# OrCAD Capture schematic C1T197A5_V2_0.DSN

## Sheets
1 00_Log: title: Telink-Semi; rev: V2.0; note: C1T197A5
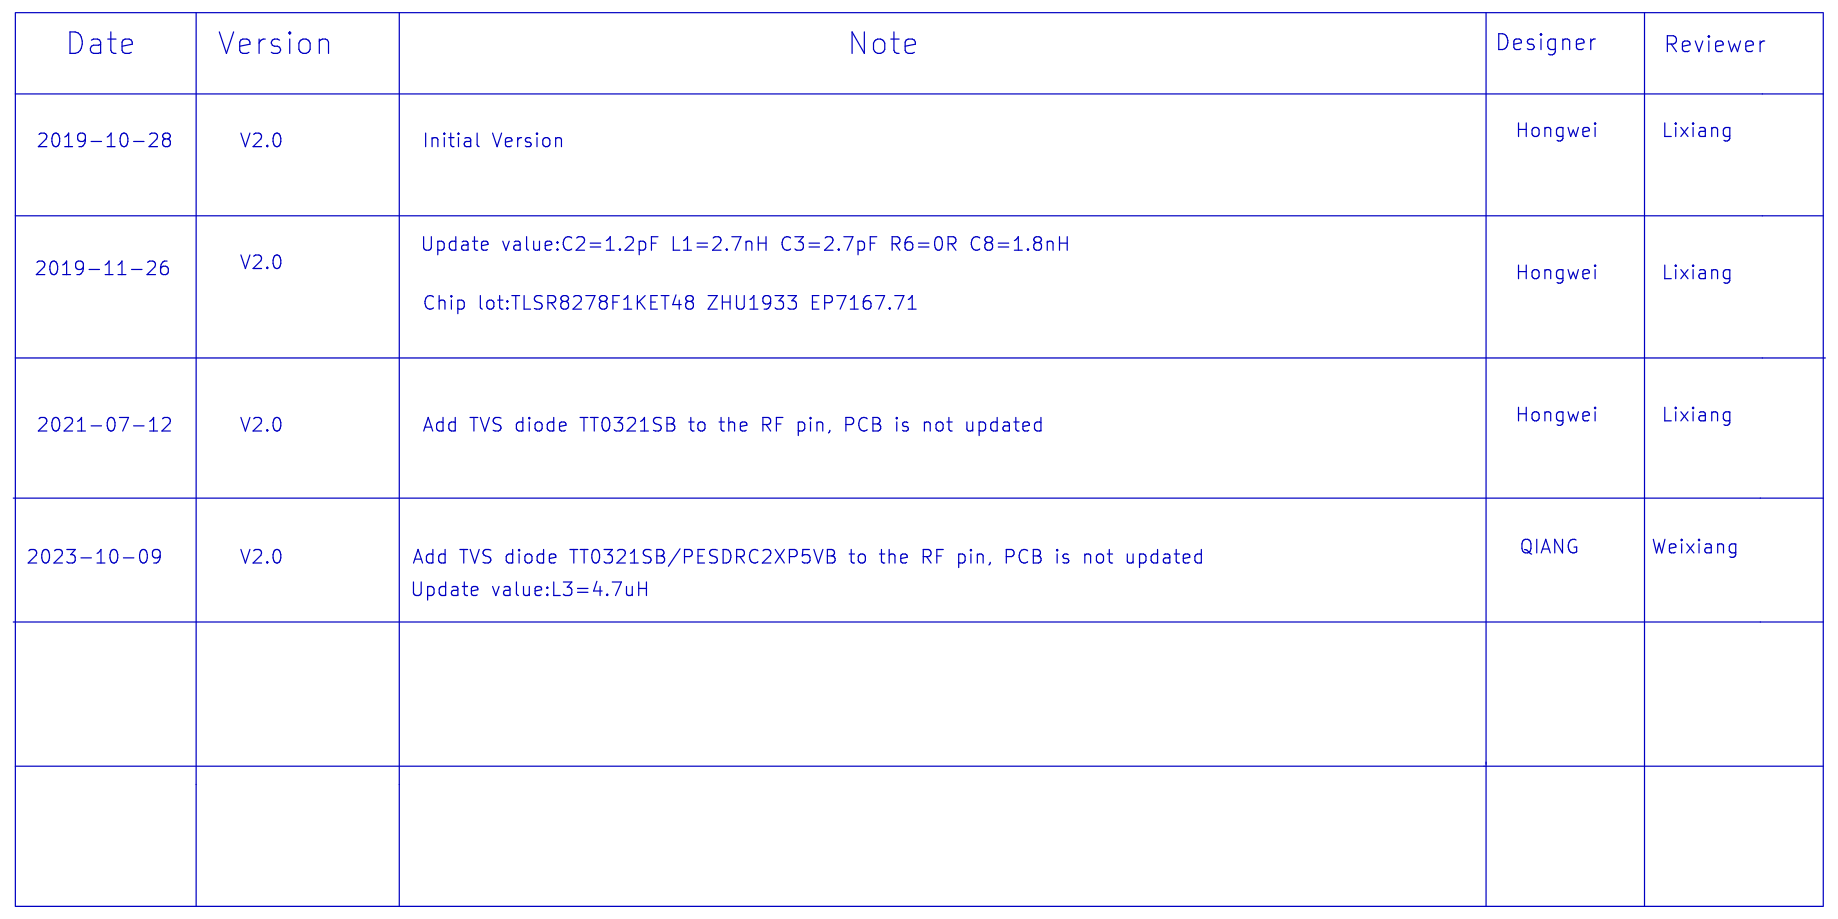
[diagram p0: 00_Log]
2 01_CPU: size A4
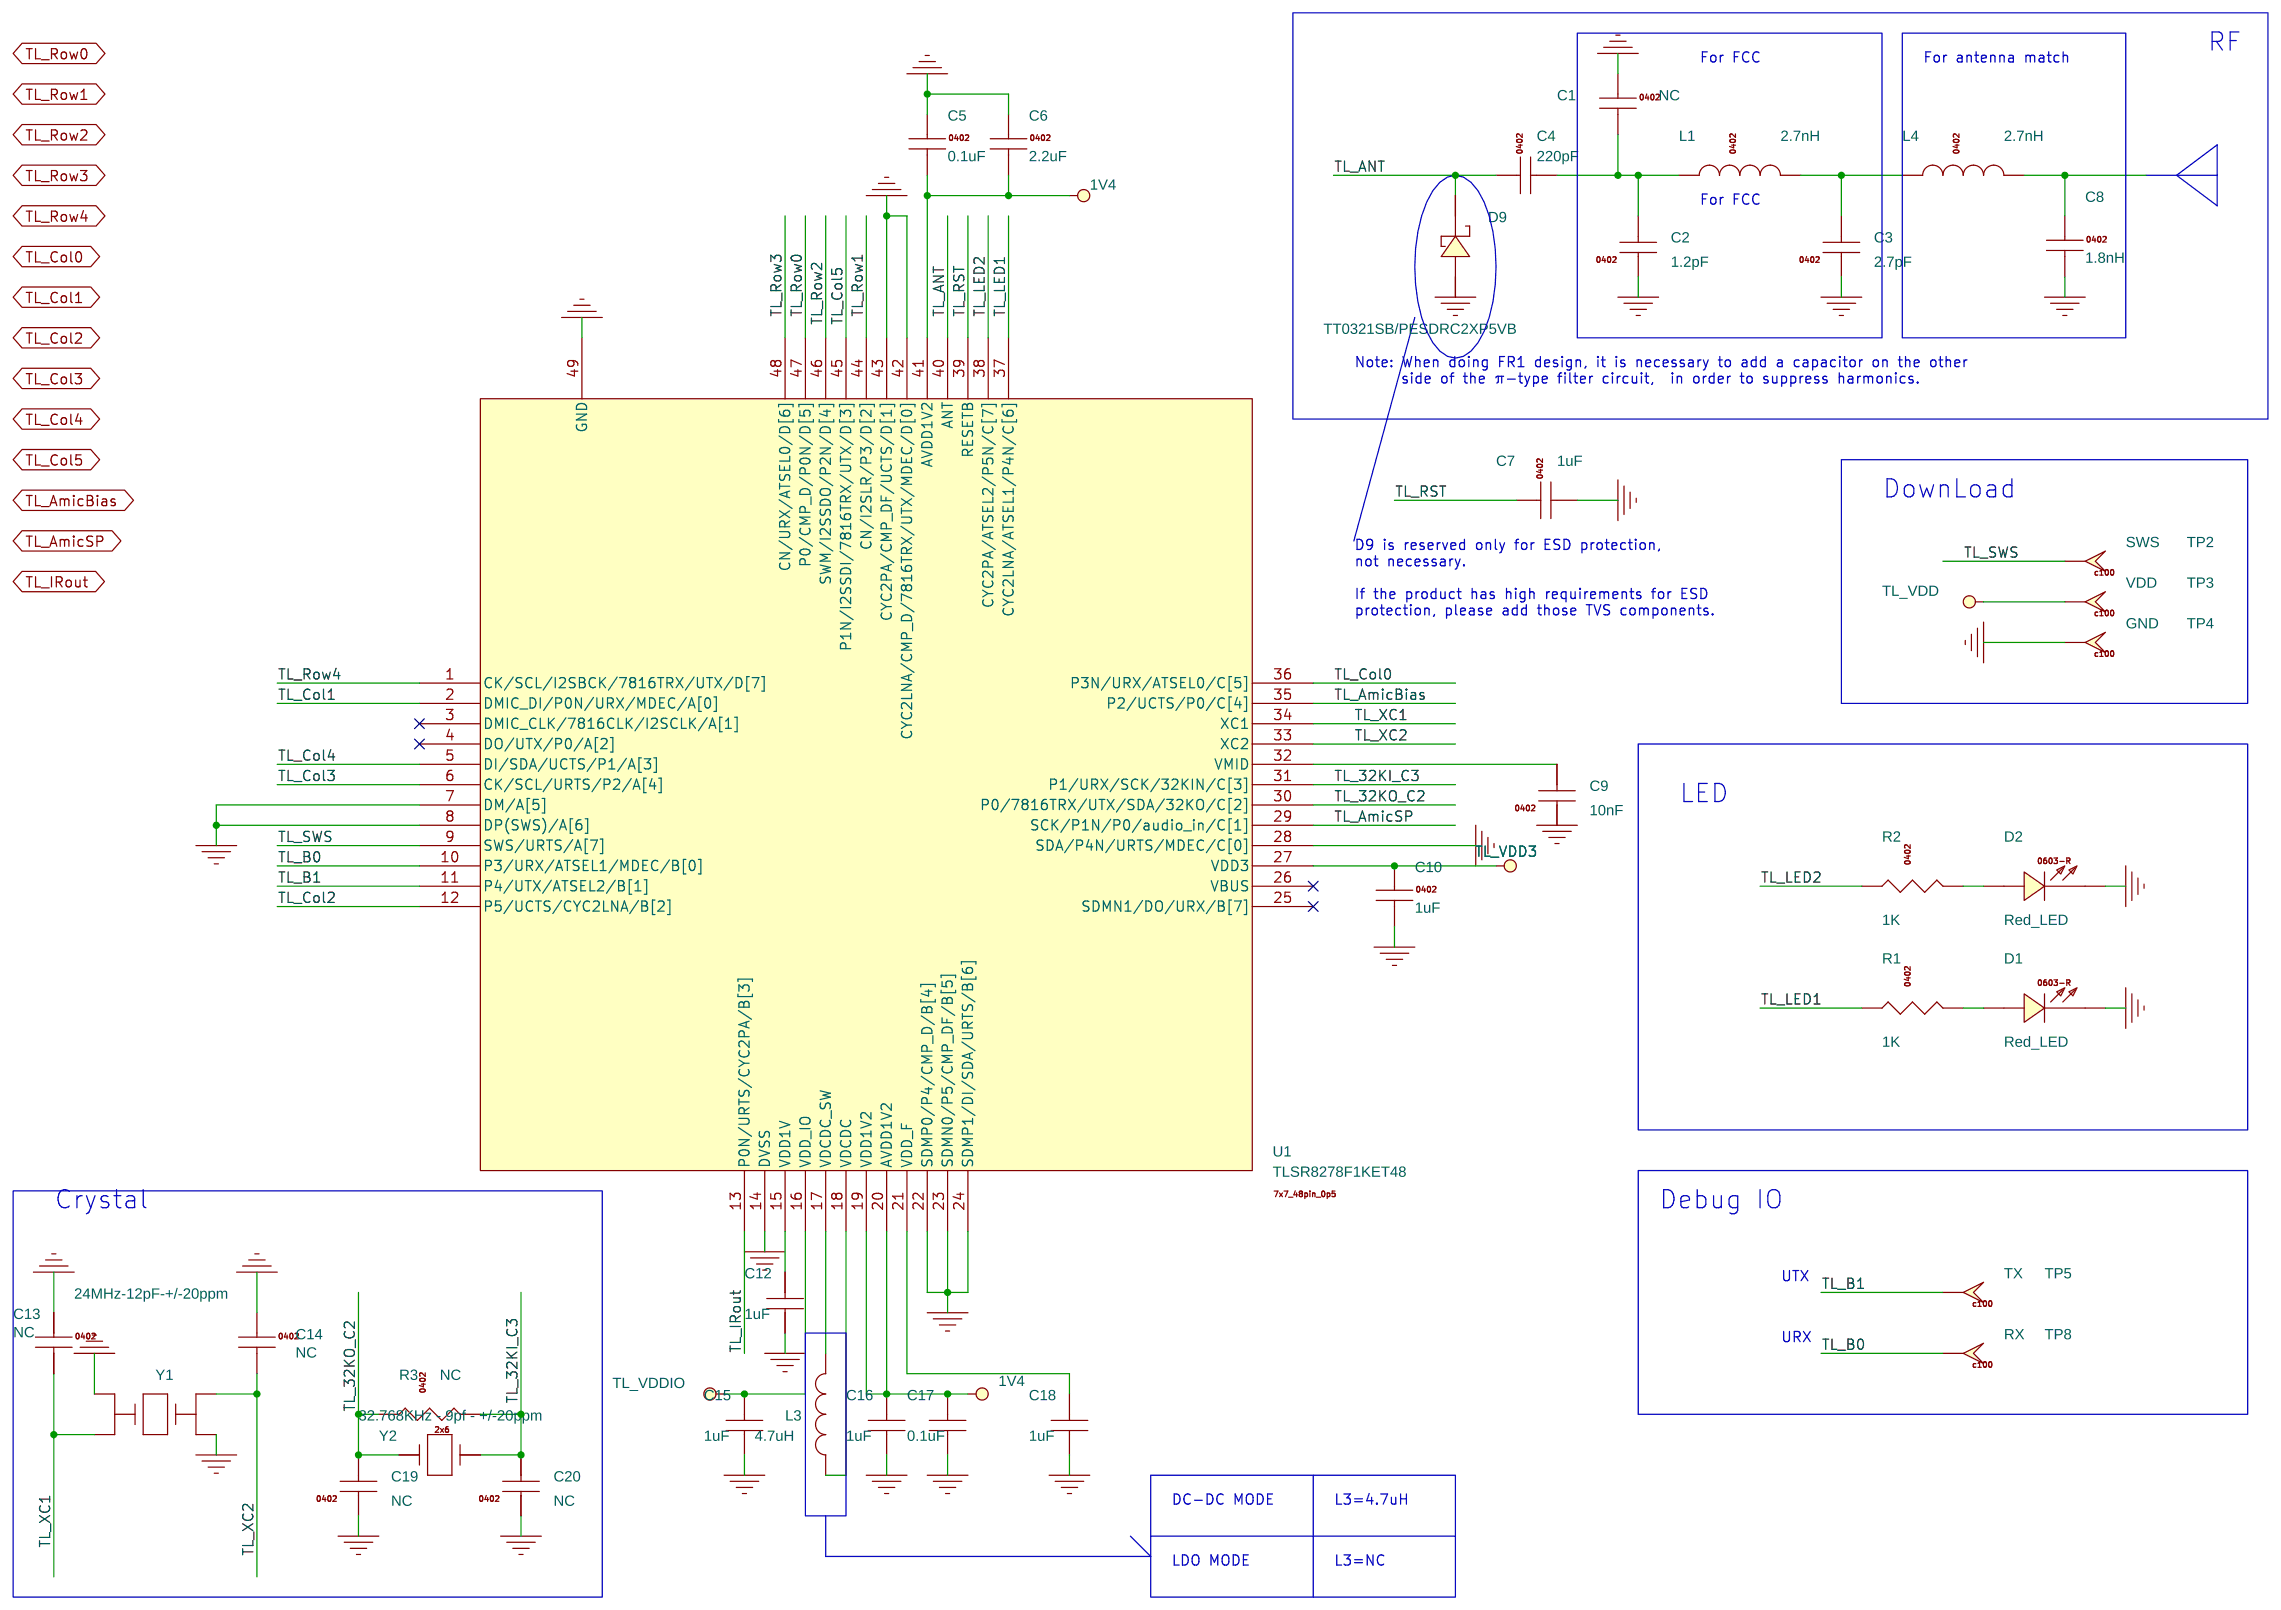
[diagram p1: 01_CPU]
3 02_Key: size A4
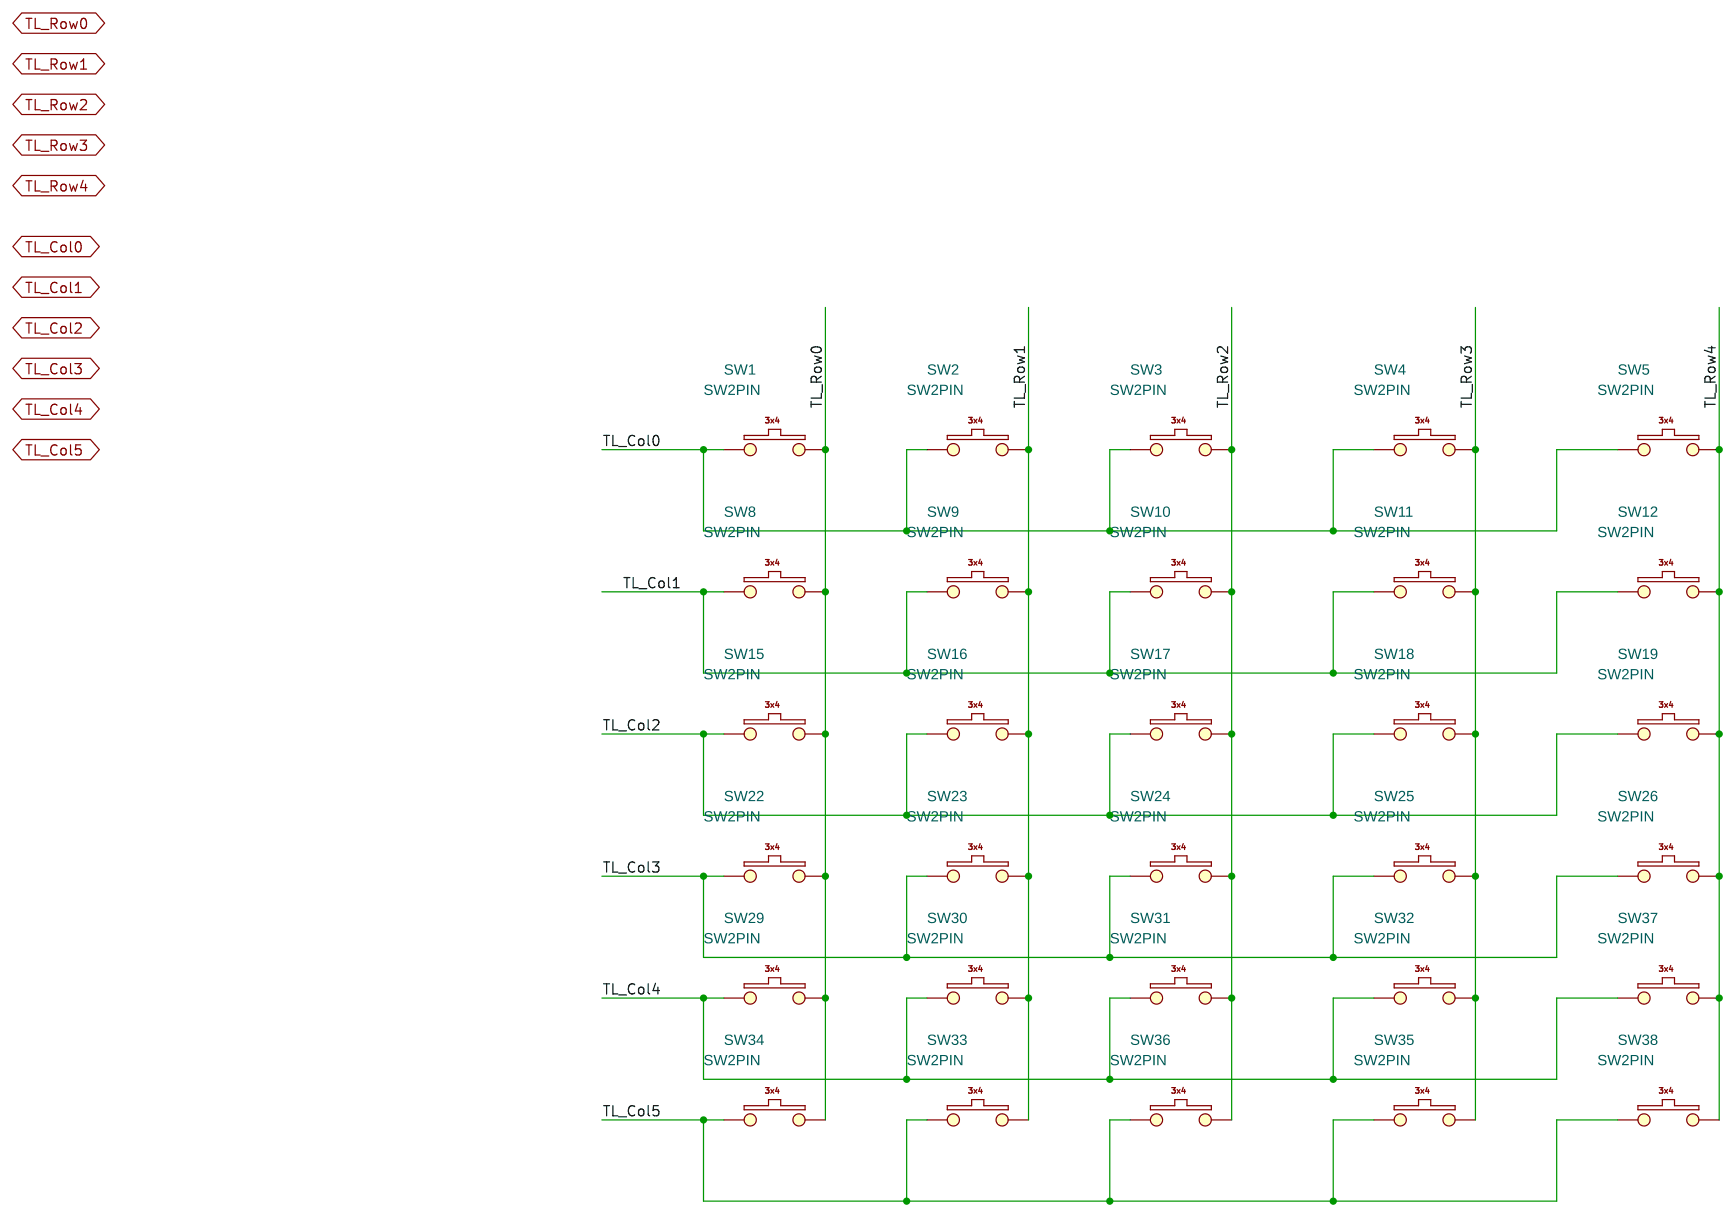
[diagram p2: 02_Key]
4 03_Others: size A4
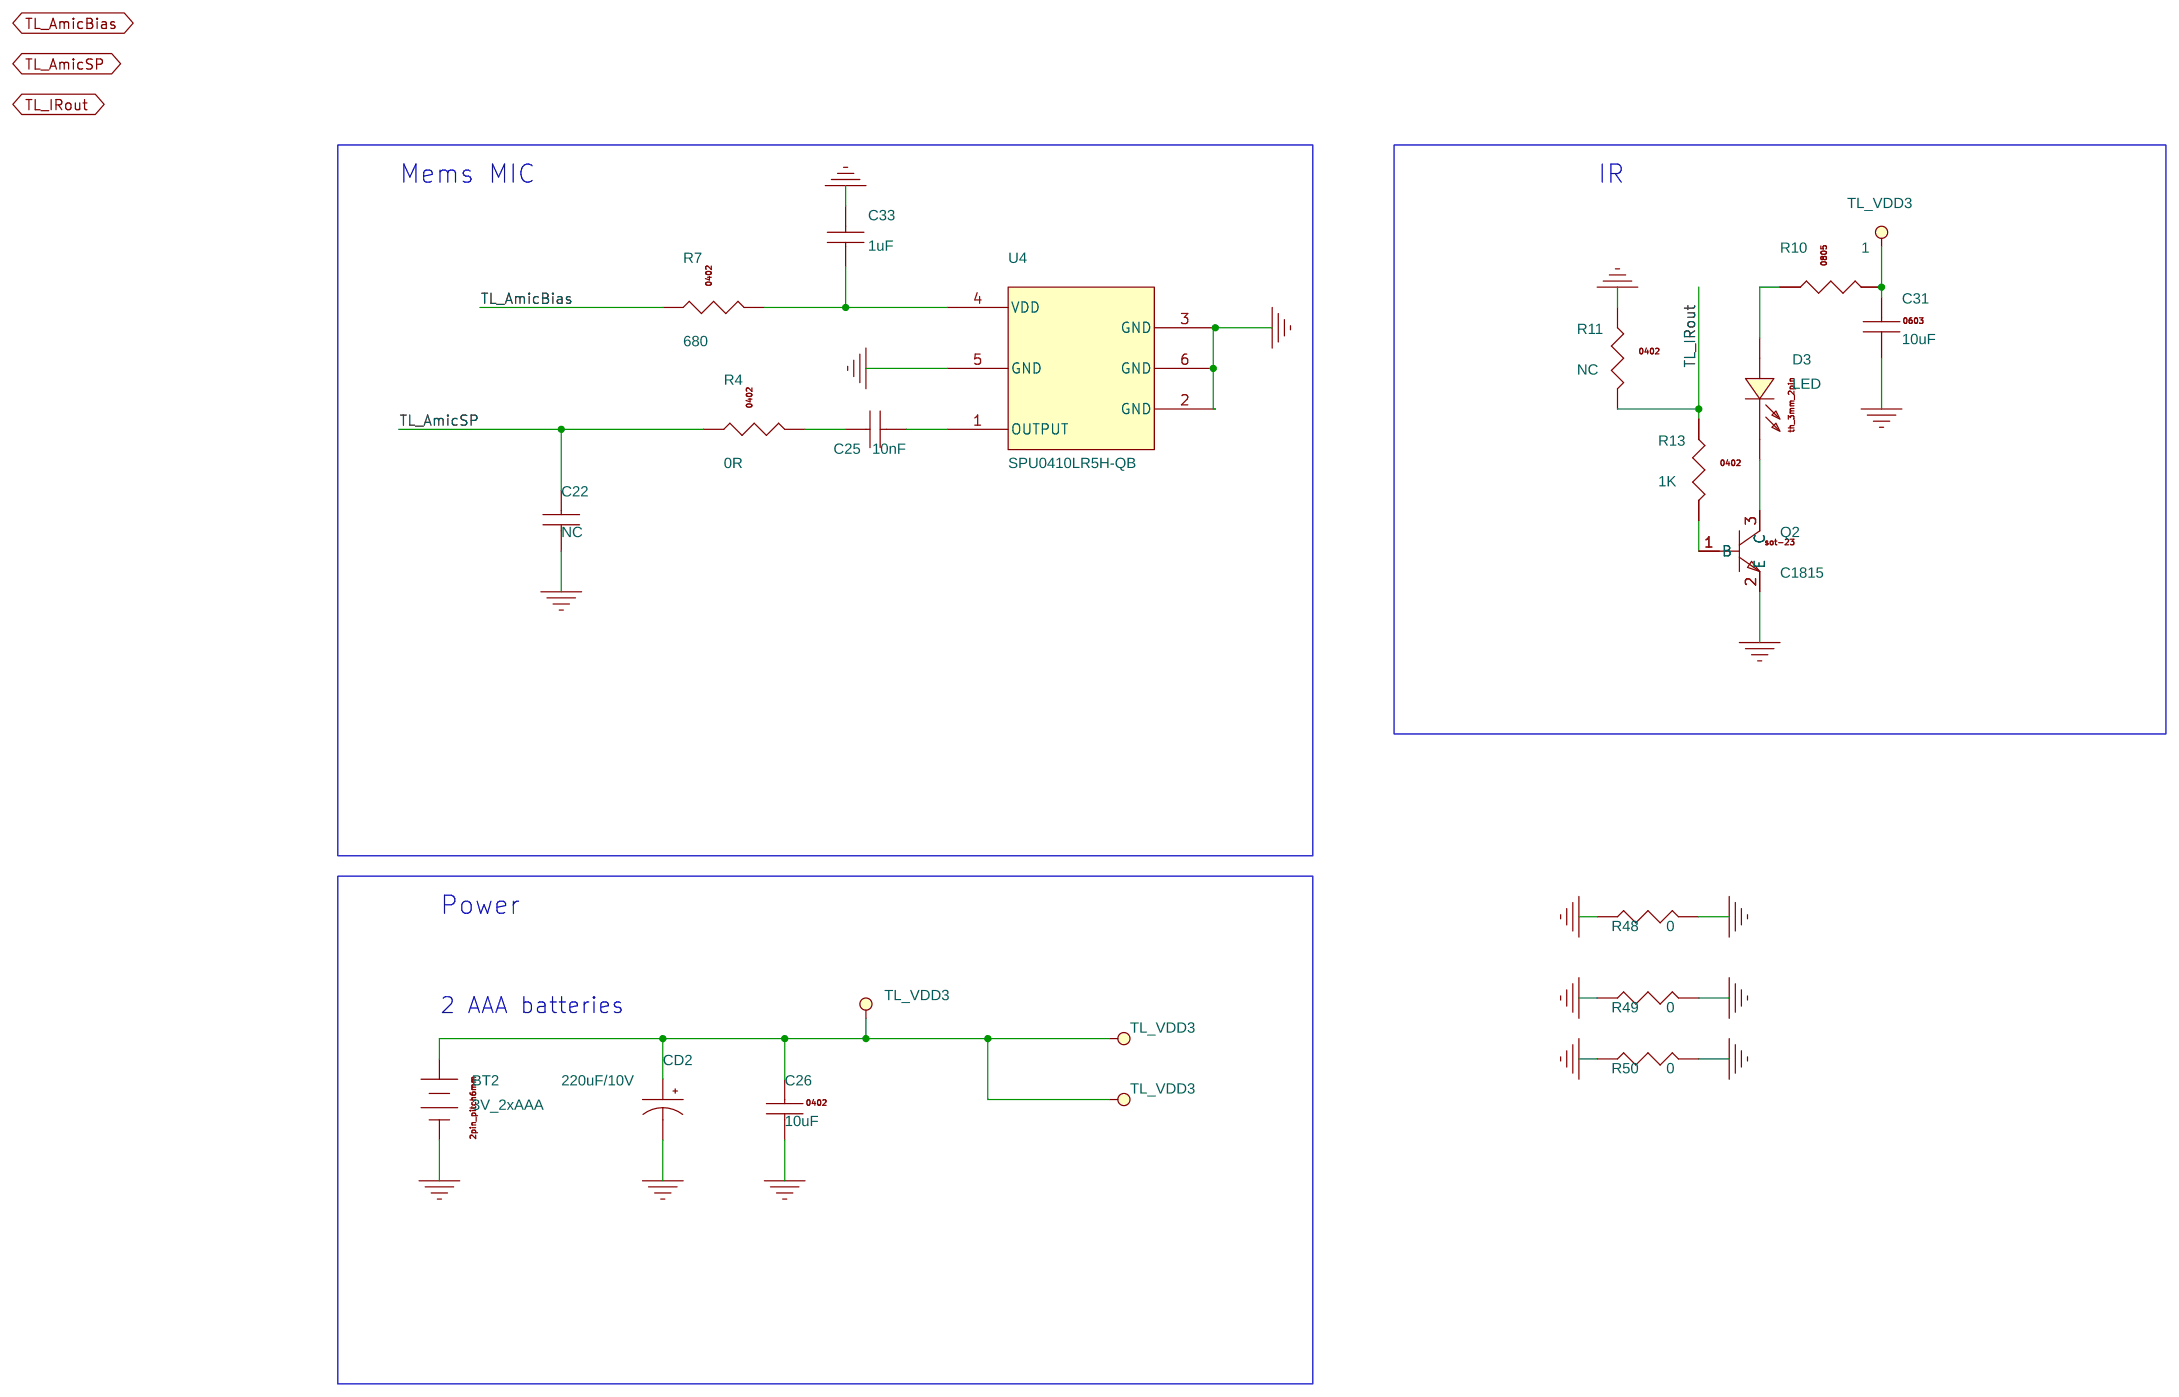
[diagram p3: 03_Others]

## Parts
sheet 01_CPU
C1  NC  [0402]
C2  1.2pF  [0402]
C3  2.7pF  [0402]
C4  220pF  [0402]
C5  0.1uF  [0402]
C6  2.2uF  [0402]
C7  1uF  [0402]
C8  1.8nH  [0402]
C9  10nF  [0402]
C10  1uF  [0402]
C12  1uF  [0402]
C13  NC  [0402]
C14  NC  [0402]
C15  1uF  [0402]
C16  1uF  [0402]
C17  0.1uF  [0402]
C18  1uF  [0402]
C19  NC  [0402]
C20  NC  [0402]
D1  Red_LED  [1206-LED]
D2  Red_LED  [1206-LED]
D9  TT0321SB/PESDRC2XP5VB  [SOD-123]
L1  2.7nH  [0402]
L3  4.7uH  [0805L]
L4  2.7nH  [0402]
R1  1K  [0402]
R2  1K  [0402]
R3  NC  [0402]
TP2  SWS  [tp100]
TP3  VDD  [tp100]
TP4  GND  [tp100]
TP5  TX  [tp100]
TP8  RX  [tp100]
U1  TLSR8278F1KET48  [qfn_7x7_48pin_0p5_4p20x4p20]
Y1  24MHz-12pF-+/-20ppm  [OSCCC250X320X110]
Y2  32.768KHz - 9pf - +/-20ppm  [OSC_2X6_SMT]
sheet 02_Key
SW1  SW2PIN  [KEY1]
SW2  SW2PIN  [key1]
SW3  SW2PIN  [key1]
SW4  SW2PIN  [key1]
SW5  SW2PIN  [key1]
SW8  SW2PIN  [key1]
SW9  SW2PIN  [key1]
SW10  SW2PIN  [key1]
SW11  SW2PIN  [key1]
SW12  SW2PIN  [key1]
SW15  SW2PIN  [key1]
SW16  SW2PIN  [key1]
SW17  SW2PIN  [key1]
SW18  SW2PIN  [key1]
SW19  SW2PIN  [key1]
SW22  SW2PIN  [key1]
SW23  SW2PIN  [key1]
SW24  SW2PIN  [key1]
SW25  SW2PIN  [key1]
SW26  SW2PIN  [key1]
SW29  SW2PIN  [key1]
SW30  SW2PIN  [key1]
SW31  SW2PIN  [key1]
SW32  SW2PIN  [key1]
SW33  SW2PIN  [key1]
SW34  SW2PIN  [key1]
SW35  SW2PIN  [key1]
SW36  SW2PIN  [key1]
SW37  SW2PIN  [key1]
SW38  SW2PIN  [key1]
sheet 03_Others
BT2  3V_2xAAA  [bat_2dip]
C22  NC  [0402]
C25  10nF  [0603c]
C26  10uF  [0603c]
C31  10uF  [0603c]
C33  1uF  [0603c]
CD2  220uF/10V  [cd2p0_4p0b1]
D3  LED  [LED_SMD_2P54MM_2PIN]
Q2  C1815  [SOT-23]
R4  0R  [0402]
R7  680  [0603r]
R10  1  [0402]
R11  NC  [0402]
R13  1K  [0402]
R48  0  [1206R]
R49  0  [1206R]
R50  0  [1206R]
U4  SPU0410LR5H-QB  [SPU0410LR5H-QB]

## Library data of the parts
C1 = C1608_NC_8
C2 = C1608_NC_2
C3 = C1608_NC_6
C4 = C1608_NC_5
C5-C7 C9 C10 = C1005X5R1C104K
C8 = C1608_NC_7
C12 C15-C18 C25 = C1005X5R1C105K
C13 C14 = C1005_NC
C19 = C1608_NC_3
C20 = C1608_NC_4
D1 D2 = 0603D_Red
D9 = DIODE_SCHOTTKY_0
L1 L4 = MLK1608_0
L3 = IND_0
R1 R2 R4 R7 = RS0402K472JT
R3 = RS0603K102JT_0
TP2-TP5 TP8 = TestPad100
U1 = TLSR8278F1KET48_0
Y1 = CRYSTAL4_SM_0
Y2 = OSC_2x6_2pin_16Mhz
SW1-SW5 SW8-SW12 SW15-SW19 SW22-SW26 SW29-SW38 = SW2PIN_0
BT2 = BATTERY_2xAAA_3V
C22 = C1005C0G1H223J
C26 = C1608X5R0J106M_0
C31 = C1608X5R1A226M
C33 = C1608X5R0J106M
CD2 = CD_220uF_16V
D3 = Led_Th_3mm_1
Q2 = NPN_C1815
R10 = RS0805K1R0JT
R11 = RS0402_NC
R13 = RS0402K101JT
R48-R50 = RS1206_NC
U4 = MULPS4CX-RM5_1

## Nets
1V4: C5.2 C6.2 C16.2 C17.2 U1.19(VDD1V2) U1.20(AVDD1V2) U1.41(AVDD1V2)
GND: BT2.2(-) C1.1 C2.1 C3.1 C5.1 C6.1 C7.2 C8.2 C9.1 C10.2 C12.1 C13.1 C14.1 C15.1 C16.1 C17.1 C18.1 C19.1 C20.1 C22.2 C26.2 C31.2 C33.2 CD2.2 D1.C(CATHODE) D2.C(CATHODE) D9.A(ANODE) Q2.2(E) R11.1 R48.1 R48.2 R49.1 R49.2 R50.1 R50.2 TP4.1(TP) U1.7(DM/A[5]) U1.8(DP(SWS)/A[6]) U1.14(DVSS) U1.22(SDMP0/P4/CMP_D/B[4]) U1.23(SDMN0/P5/CMP_DF/B[5]) U1.24(SDMP1/DI/SDA/URTS/B[6]) U1.28(SDA/P4N/URTS/MDEC/C[0]) U1.42(CYC2LNA/CMP_D/7816TRX/UTX/MDEC/D[0]) U1.43(CYC2PA/CMP_DF/UCTS/D[1]) U1.49(GND) U4.2(GND) U4.3(GND) U4.5(GND) U4.6(GND) Y1.2 Y1.4
TL_32KI_C3: C20.2 R3.2 U1.31(P1/URX/SCK/32KIN/C[3]) Y2.2
TL_32KO_C2: C19.2 R3.1 U1.30(P0/7816TRX/UTX/SDA/32KO/C[2]) Y2.1
TL_AmicBias: U1.35(P2/UCTS/P0/C[4])
TL_AmicBias (page 03_Others): R7.1
TL_AmicSP: U1.29(SCK/P1N/P0/audio_in/C[1])
TL_AmicSP (page 03_Others): C22.1 R4.1
TL_ANT: C4.1 D9.C(CATHODE) U1.40(ANT)
TL_B0: TP8.1(TP) U1.10(P3/URX/ATSEL1/MDEC/B[0])
TL_B1: TP5.1(TP) U1.11(P4/UTX/ATSEL2/B[1])
TL_Col0: U1.36(P3N/URX/ATSEL0/C[5])
TL_Col0 (page 02_Key): SW1.1 SW2.1 SW3.1 SW4.1 SW5.1
TL_Col1: U1.2(DMIC_DI/P0N/URX/MDEC/A[0])
TL_Col1 (page 02_Key): SW8.1 SW9.1 SW10.1 SW11.1 SW12.1
TL_Col2: U1.12(P5/UCTS/CYC2LNA/B[2])
TL_Col2 (page 02_Key): SW15.1 SW16.1 SW17.1 SW18.1 SW19.1
TL_Col3: U1.6(CK/SCL/URTS/P2/A[4])
TL_Col3 (page 02_Key): SW22.1 SW23.1 SW24.1 SW25.1 SW26.1
TL_Col4: U1.5(DI/SDA/UCTS/P1/A[3])
TL_Col4 (page 02_Key): SW29.1 SW30.1 SW31.1 SW32.1 SW37.1
TL_Col5: U1.45(P1N/I2SSDI/7816TRX/UTX/D[3])
TL_Col5 (page 02_Key): SW33.1 SW34.1 SW35.1 SW36.1 SW38.1
TL_IRout: U1.13(P0N/URTS/CYC2PA/B[3])
TL_IRout (page 03_Others): R11.2 R13.1
TL_LED1: R1.1 U1.37(CYC2LNA/ATSEL1/P4N/C[6])
TL_LED2: R2.1 U1.38(CYC2PA/ATSEL2/P5N/C[7])
TL_Row0: U1.47(P0/CMP_D/P0N/D[5])
TL_Row0 (page 02_Key): SW1.2 SW8.2 SW15.2 SW22.2 SW29.2 SW34.2
TL_Row1: U1.44(CN/I2SLR/P3/D[2])
TL_Row1 (page 02_Key): SW2.2 SW9.2 SW16.2 SW23.2 SW30.2 SW33.2
TL_Row2: U1.46(SWM/I2SSDO/P2N/D[4])
TL_Row2 (page 02_Key): SW3.2 SW10.2 SW17.2 SW24.2 SW31.2 SW36.2
TL_Row3: U1.48(CN/URX/ATSEL0/D[6])
TL_Row3 (page 02_Key): SW4.2 SW11.2 SW18.2 SW25.2 SW32.2 SW35.2
TL_Row4: U1.1(CK/SCL/I2SBCK/7816TRX/UTX/D[7])
TL_Row4 (page 02_Key): SW5.2 SW12.2 SW19.2 SW26.2 SW37.2 SW38.2
TL_RST: C7.1 U1.39(RESETB)
TL_SWS: TP2.1(TP) U1.9(SWS/URTS/A[7])
TL_VDD: BT2.1(+) C10.1 C15.2 C26.1 C31.1 CD2.1 R10.2 TP3.1(TP) U1.16(VDD_IO) U1.27(VDD3)
TL_XC1: C13.2 U1.34(XC1) Y1.3
TL_XC2: C14.2 U1.33(XC2) Y1.1
N21000893: D2.A(ANODE) R2.2
N21007782: D1.A(ANODE) R1.2
N21115397: C8.1 L4.2
N21115407: C1.2 C2.2 C4.2 L1.1
N21115415: C3.2 L1.2 L4.1
N21116055: C12.2 U1.15(VDD1V)
N21116211: L3.2 U1.17(VDCDC_SW)
N21116214: L3.1 U1.18(VDCDC)
N21116508: C18.2 U1.21(VDD_F)
N21117063: C9.2 U1.32(VMID)
N21140224: C25.2 U4.1(OUTPUT)
N21140411: C33.1 R7.2 U4.4(VDD)
N21149600: C25.1 R4.2
N21152572: D3.A(ANODE) R10.1
N21152638: Q2.1(B) R13.2
N21152650: D3.C(CATHODE) Q2.3(C)

Not connected (* = marked no-connect by the designer): U1 3(DMIC_CLK/7816CLK/I2SCLK/A[1])* 4(DO/UTX/P0/A[2])* 25(SDMN1/DO/URX/B[7])* 26(VBUS)*

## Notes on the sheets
sheet 1
- Date
- Version
- Note
- Designer
- Reviewer
- 2019-10-28
- V2.0
- Initial Version
- Hongwei
- Lixiang
- V2.0
- Update value:C2=1.2pF L1=2.7nH C3=2.7pF R6=0R C8=1.8nH
- 2019-11-26
- Hongwei
- Lixiang
- Chip lot:TLSR8278F1KET48 ZHU1933 EP7167.71
- 2021-07-12
- V2.0
- Add TVS diode TT0321SB to the RF pin, PCB is not updated
- Hongwei
- Lixiang
- QIANG
- Weixiang
- 2023-10-09
- V2.0
- Add TVS diode TT0321SB/PESDRC2XP5VB to the RF pin, PCB is not updated
- Update value:L3=4.7uH
sheet 2
- RF
- For FCC
- For antenna match
- For FCC
- Note: When doing FR1 design, it is necessary to add a capacitor on the other
        side of the π-type filter circuit,  in order to suppress harmonics.
- DownLoad
- D9 is reserved only for ESD protection,
  not necessary.
  If the product has high requirements for ESD
  protection, please add those TVS components.
- LED
- Crystal
- Debug IO
- UTX
- URX
- DC-DC MODE
- L3=4.7uH
- LDO MODE
- L3=NC
sheet 4
- Mems MIC
- IR
- Power
- 2 AAA batteries
